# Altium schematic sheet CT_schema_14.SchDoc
size 145 x 119 mm
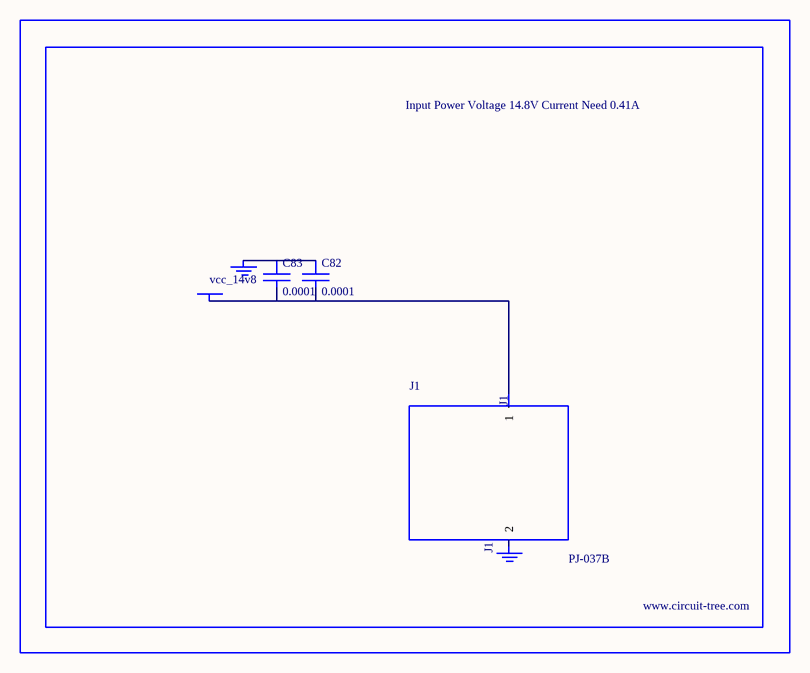
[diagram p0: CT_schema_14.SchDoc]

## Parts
BORDER13  (no value)
C82  0.0001  [EXV-9H]
C83  0.0001  [EXV-9H]
GND_INSTANCE_13_0  (no value)
GND_INSTANCE_13_1  (no value)
J1  PJ-037B  [PJ-037B_PACKAGE]
POWER_INSTANCE_13_0  vcc_14v8

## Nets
NetC82_1: C82.1 C83.1 GND_INSTANCE_13_0.0(GND)
NetC82_2: C82.2 C83.2 J1.1 POWER_INSTANCE_13_0.0(PWR)

Not connected (* = marked no-connect by the designer): GND_INSTANCE_13_1 0(GND); J1 2

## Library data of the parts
BORDER13 = BORDER_PAGE13
C82 C83 = EDK107M035A9HAA
GND_INSTANCE_13_0 GND_INSTANCE_13_1 = GND
POWER_INSTANCE_13_0 = PWR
